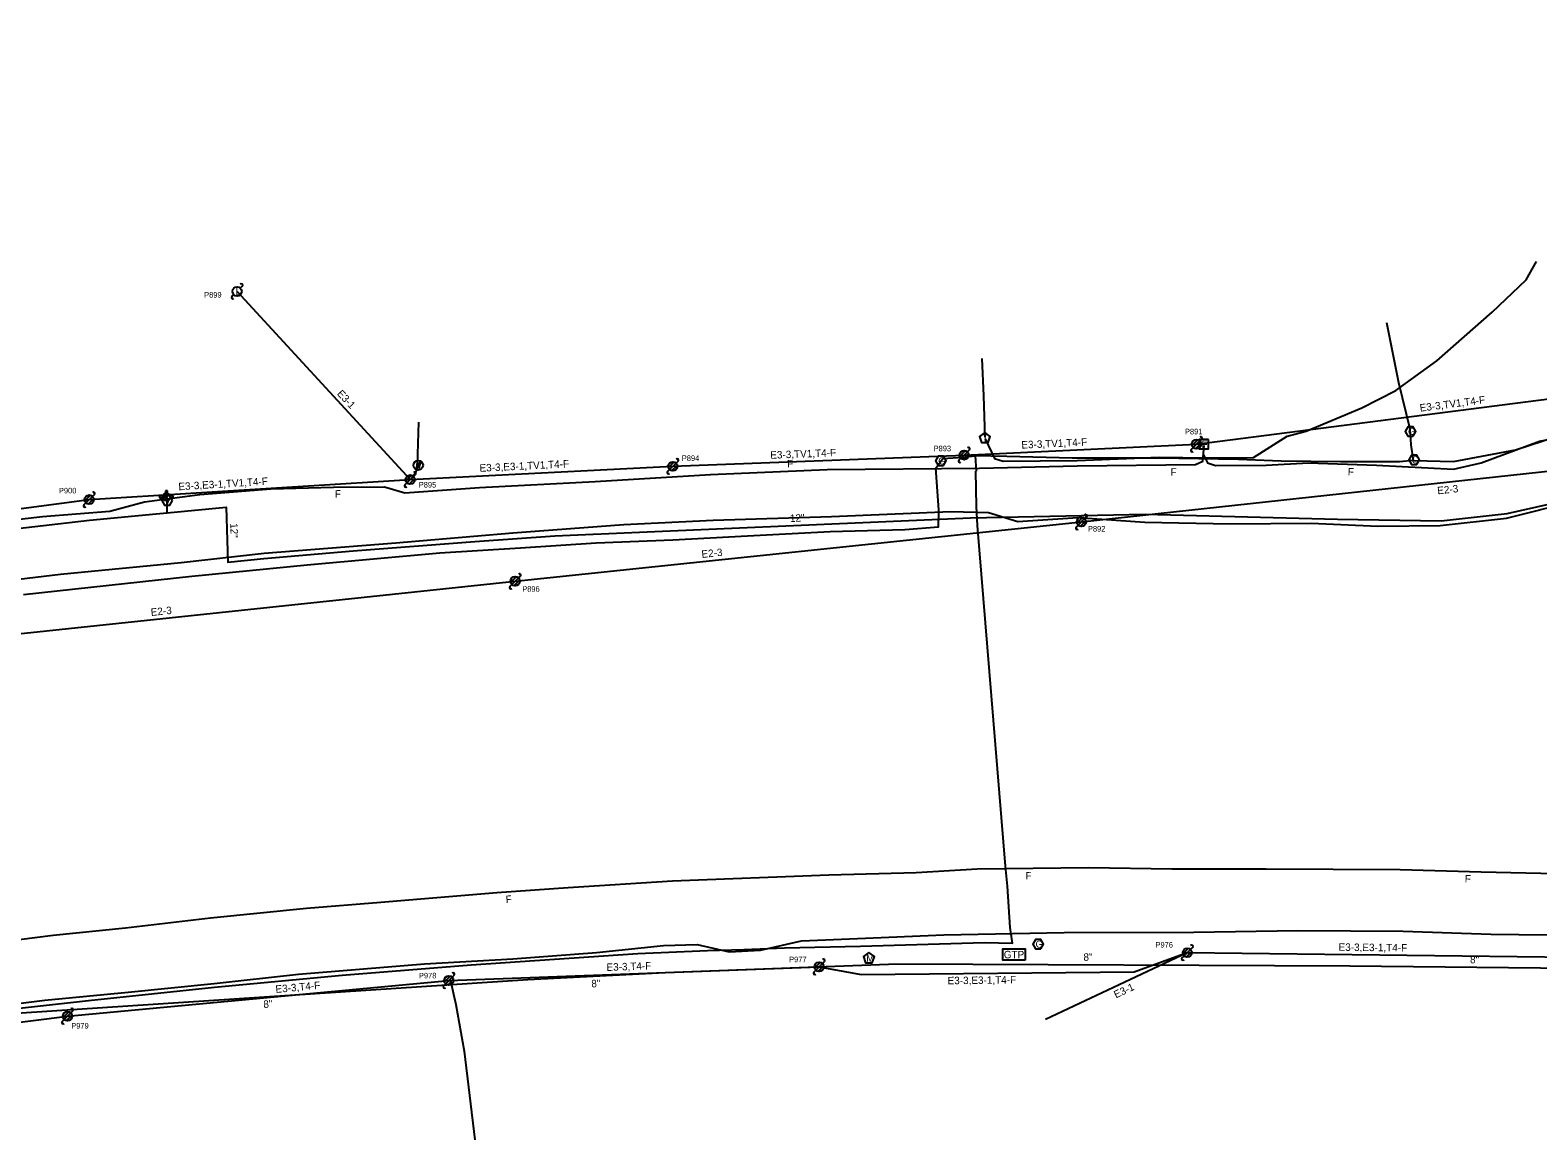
# Model space of a CAD drawing. Extents: x 1741604 to 1825760, y 1164229 to 1194908.
# Drawn here: x 1797796 to 1798607, y 1188088 to 1188684 of the extents above; entities that cross this region are included whole.
import ezdxf

# ---------------------------------------------------------------- set-up
doc = ezdxf.new("R2010")
doc.units = 0
for name, color, linetype in [('RD_EX_SU_Elec', 7, 'Continuous'), ('RD_EX_SU_Gas', 7, 'Continuous'), ('RD_EX_SU_H2O', 7, 'Continuous'), ('RD_EX_SU_Ovhd', 7, 'Continuous'), ('RD_EX_SU_Pole', 7, 'Continuous'), ('RD_EX_SU_Telecom', 7, 'Continuous'), ('RD_EX_SU_TX_H2O', 7, 'Continuous'), ('RD_EX_SU_TX_Pole', 7, 'Continuous'), ('RD_EX_SU_TX_Telecom', 7, 'Continuous')]:
    doc.layers.add(name, color=color, linetype=linetype)

# ---------------------------------------------------------------- blocks, each defined once
blk = doc.blocks.new('SUE_WM')
at = {"layer": 'RD_EX_SU_H2O'}
blk.add_lwpolyline([(0, 3.05), (-2.9, 0.94), (-1.79, -2.47), (1.79, -2.47), (2.9, 0.94)], close=True, dxfattribs=at)
blk.add_text('M', height=3.75, dxfattribs=at).set_placement((-1.43, -1.88))
blk = doc.blocks.new('SUE_GVC')
at = {"layer": 'RD_EX_SU_Gas'}
blk.add_lwpolyline([(1.44, -2.5), (2.89, 0), (1.44, 2.5), (-1.44, 2.5), (-2.89, 0), (-1.44, -2.5)], close=True, dxfattribs=at)
blk.add_text('G', height=3.75, dxfattribs=at).set_placement((-1.34, -1.88))
blk = doc.blocks.new('SUE_TPP')
at = {"layer": 'RD_EX_SU_Telecom'}
blk.add_lwpolyline([(0, 3), (-2.85, 0.93), (-1.76, -2.43), (1.76, -2.43), (2.85, 0.93)], close=True, dxfattribs=at)
blk.add_text('T', height=3.75, dxfattribs=at).set_placement((-1.25, -1.88))
blk = doc.blocks.new('SUE_ETM')
at = {"layer": 'RD_EX_SU_Elec'}
blk.add_lwpolyline([(1.24, 2.04), (0.23, -1.41), (-0.27, 0.46), (-1.03, -2.36), (-0.34, 1.55), (0.22, -0.39)], close=True, dxfattribs=at)
blk.add_circle((0, 0), 2.55, dxfattribs=at)
blk = doc.blocks.new('SUE_WFH')
at = {"layer": 'RD_EX_SU_H2O'}
for p, q in [((-2.01, 0.6), (-3.65, 0.6)), ((-3.65, 0.6), (-3.65, -0.45)), ((-0.48, 3.38), (-0.48, 2.04)), ((0.57, 3.38), (-0.48, 3.38)), ((0.57, 2.02), (0.57, 3.38)), ((3.7, 0.6), (2.01, 0.6)), ((3.7, -0.45), (3.7, 0.6)), ((-3.65, -0.45), (-2.05, -0.45)), ((2.05, -0.45), (3.7, -0.45))]:
    blk.add_line(p, q, dxfattribs=at)
for radius in [2.1, 0.263]:
    blk.add_circle((0, 0), radius, dxfattribs=at)
for start, end in [(163.3387, 192.31502), (74.24552, 103.21276), (347.68498, 16.6613)]:
    blk.add_arc((0, 0), 2.1, start, end, dxfattribs=at)
blk = doc.blocks.new('SUE_WV')
at = {"layer": 'RD_EX_SU_H2O'}
blk.add_lwpolyline([(2.89, 0), (1.44, 2.5), (-1.44, 2.5), (-2.89, 0), (-1.44, -2.5), (1.44, -2.5)], close=True, dxfattribs=at)
blk.add_text('V', height=3.75, dxfattribs=at).set_placement((-1.43, -1.88))

msp = doc.modelspace()

# ---------------------------------------------------------------- linework, layer by layer
at = {"layer": 'RD_EX_SU_Elec'}
for points in [[(1798004.79, 1188453.04), (1798004.66, 1188456.54), (1798005.22, 1188473.7)], [(1798001.22, 1188443.24), (1798003.9, 1188447.11), (1798004.24, 1188448.38)], [(1798022.26, 1188173.57), (1798025.16, 1188160.75), (1798029.65, 1188135.73), (1798035.41, 1188088.07)]]:
    msp.add_lwpolyline(points, dxfattribs=at)
at = {"layer": 'RD_EX_SU_Gas'}
for points in [[(1798540.02, 1188453.1), (1798561.42, 1188452.55), (1798594.68, 1188458.87), (1798616.68, 1188465.98), (1798635.5, 1188476.83), (1798669.38, 1188491.43), (1798687.92, 1188501.53), (1798704.5, 1188511.11), (1798719.12, 1188521.68), (1798742.22, 1188540.09), (1798758.9, 1188555.78), (1798774.34, 1188572.88), (1798802.43, 1188609.18), (1798819.17, 1188635.67), (1798831.94, 1188665.33), (1798832.73, 1188675.73)], [(1798525.4, 1188527.29), (1798531.86, 1188494.99), (1798537.92, 1188470.06), (1798538.41, 1188461.43), (1798539.71, 1188453.05), (1798532.32, 1188452.41), (1798500.7, 1188452.29), (1798468.81, 1188452.77), (1798445.87, 1188453.58), (1798402.97, 1188454.26), (1798356.44, 1188454.27), (1798321.29, 1188455.26), (1798304.33, 1188455.51)], [(1797792.89, 1188381.02), (1797883.32, 1188390.89), (1797945.19, 1188396.98), (1798016.59, 1188403.44), (1798059.98, 1188406.18), (1798100.51, 1188408.83), (1798141.81, 1188410.44), (1798181.84, 1188412.52), (1798226.38, 1188414.99), (1798266.44, 1188416.08), (1798284.61, 1188417.5), (1798284.71, 1188426.53), (1798283.11, 1188448.99), (1798286.92, 1188454.19), (1798297.89, 1188454.93), (1798304.33, 1188455.51), (1798304.77, 1188447.27)], [(1797738.94, 1188153.06), (1797827.69, 1188162.92), (1797895.38, 1188170.03), (1797964.13, 1188176.5), (1798033.35, 1188182.12), (1798122.93, 1188188.15), (1798160.35, 1188189.8), (1798179.98, 1188190.39), (1798201.78, 1188191.3), (1798242.62, 1188192.13), (1798309.37, 1188194.16), (1798324.41, 1188193.75), (1798323.14, 1188202.23), (1798321.69, 1188224.33), (1798320.58, 1188235.17), (1798305.62, 1188418.09), (1798304.96, 1188428.39), (1798304.62, 1188447.39)]]:
    msp.add_lwpolyline(points, dxfattribs=at)
msp.add_lwpolyline([(1798331.09, 1188184.62), (1798319.09, 1188184.62), (1798319.09, 1188190.62), (1798331.09, 1188190.62)], close=True, dxfattribs=at)
at = {"layer": 'RD_EX_SU_H2O'}
for p, q in [((1798301.72, 1188422.21), (1798395.66, 1188424.19)), ((1798078.39, 1188412.53), (1798301.72, 1188422.21)), ((1798137.61, 1188177.95), (1798262.58, 1188182.7)), ((1798262.58, 1188182.7), (1798505.66, 1188181.64)), ((1798505.66, 1188181.64), (1798756.83, 1188179)), ((1797651.95, 1188147.16), (1798063.79, 1188174.26)), ((1798063.79, 1188174.26), (1798137.61, 1188177.95))]:
    msp.add_line(p, q, dxfattribs=at)
for points in [[(1798395.66, 1188424.19), (1798464.51, 1188422.44), (1798499.05, 1188421.5), (1798554.83, 1188420.73), (1798590.2, 1188424.62), (1798613.36, 1188429.79), (1798642.06, 1188437.41), (1798666.06, 1188447.65), (1798696.65, 1188463.78), (1798729.84, 1188484.09), (1798749.61, 1188498.15)], [(1797150.37, 1188316.12), (1797152.28, 1188309.78), (1797177.44, 1188315.15), (1797233.5, 1188327.84), (1797278.93, 1188337.07), (1797336.23, 1188346.78), (1797380.95, 1188356.35), (1797444.61, 1188369.17), (1797512.17, 1188378.38), (1797550.95, 1188385.16), (1797589.68, 1188391.31), (1797635.24, 1188397.02), (1797695.71, 1188404.5), (1797752.4, 1188412.16), (1797828.2, 1188420.96), (1797864.18, 1188424.5), (1797870.03, 1188425), (1797870.01, 1188429.58), (1797869.79, 1188432.74)], [(1797870.03, 1188425), (1797901.67, 1188428.06), (1797902.58, 1188398.42), (1797922.02, 1188400.35), (1797969.92, 1188404.62), (1798035.33, 1188409.61), (1798078.39, 1188412.53)]]:
    msp.add_lwpolyline(points, dxfattribs=at)
at = {"layer": 'RD_EX_SU_Ovhd'}
for p, q in [((1797907.57, 1188543.94), (1798000.66, 1188442.8)), ((1798423.29, 1188461.79), (1798648.97, 1188490.91)), ((1798141.81, 1188449.95), (1798298.38, 1188456.02)), ((1798298.38, 1188456.02), (1798423.29, 1188461.79)), ((1798361.37, 1188420.07), (1798718.12, 1188458.87)), ((1798000.66, 1188442.8), (1798141.81, 1188449.95)), ((1797828.15, 1188432.05), (1798000.66, 1188442.8)), ((1797680, 1188412.7), (1797828.15, 1188432.05)), ((1798057.02, 1188388.18), (1798361.37, 1188420.07)), ((1797704.48, 1188350.9), (1798057.02, 1188388.18)), ((1798342.15, 1188152.97), (1798418.32, 1188188.64)), ((1798418.32, 1188188.64), (1798625.21, 1188186.16)), ((1798021.47, 1188173.66), (1798220.42, 1188181.01)), ((1797816.46, 1188154.52), (1798021.47, 1188173.66)), ((1797662.12, 1188135.12), (1797816.46, 1188154.52))]:
    msp.add_line(p, q, dxfattribs=at)
msp.add_lwpolyline([(1798220.42, 1188181.01), (1798242.98, 1188176.98), (1798389.75, 1188178.38), (1798418.32, 1188188.64)], dxfattribs=at)
at = {"layer": 'RD_EX_SU_Pole'}
for p, q in [((1797909.34, 1188545.71), (1797910.4, 1188546.77)), ((1797904.74, 1188541.11), (1797905.8, 1188542.17)), ((1798420.87, 1188461.14), (1798423.93, 1188464.2)), ((1798421.52, 1188460.02), (1798425.05, 1188463.56)), ((1798425.05, 1188463.56), (1798426.12, 1188464.62)), ((1798295.96, 1188455.37), (1798299.02, 1188458.43)), ((1798296.61, 1188454.25), (1798300.15, 1188457.79)), ((1798297.73, 1188453.6), (1798300.79, 1188456.67)), ((1798300.15, 1188457.79), (1798301.21, 1188458.85)), ((1798420.46, 1188458.96), (1798421.52, 1188460.02)), ((1798422.64, 1188459.37), (1798425.7, 1188462.44)), ((1798138.99, 1188447.13), (1798140.05, 1188448.19)), ((1798139.4, 1188449.31), (1798142.46, 1188452.37)), ((1798140.05, 1188448.19), (1798143.58, 1188451.72)), ((1798141.17, 1188447.54), (1798144.23, 1188450.6)), ((1798143.58, 1188451.72), (1798144.64, 1188452.78)), ((1798295.55, 1188453.19), (1798296.61, 1188454.25)), ((1797997.83, 1188439.97), (1797998.89, 1188441.03)), ((1797998.25, 1188442.15), (1798001.31, 1188445.22)), ((1797998.89, 1188441.03), (1798002.43, 1188444.57)), ((1798000.01, 1188440.39), (1798003.08, 1188443.45)), ((1798002.43, 1188444.57), (1798003.49, 1188445.63)), ((1797825.74, 1188431.41), (1797828.8, 1188434.47)), ((1797826.38, 1188430.29), (1797829.92, 1188433.82)), ((1797827.5, 1188429.64), (1797830.57, 1188432.7)), ((1797829.92, 1188433.82), (1797830.98, 1188434.88)), ((1797825.32, 1188429.23), (1797826.38, 1188430.29)), ((1798363.14, 1188421.84), (1798364.2, 1188422.9)), ((1798358.54, 1188417.25), (1798359.6, 1188418.31)), ((1798358.95, 1188419.43), (1798362.01, 1188422.49)), ((1798359.6, 1188418.31), (1798363.14, 1188421.84)), ((1798360.72, 1188417.66), (1798363.78, 1188420.72)), ((1798054.6, 1188387.54), (1798057.66, 1188390.6)), ((1798058.78, 1188389.95), (1798059.84, 1188391.01)), ((1798054.19, 1188385.35), (1798055.25, 1188386.41)), ((1798055.25, 1188386.41), (1798058.78, 1188389.95)), ((1798056.37, 1188385.77), (1798059.43, 1188388.83)), ((1798415.9, 1188187.99), (1798418.97, 1188191.06)), ((1798416.55, 1188186.87), (1798420.09, 1188190.41)), ((1798417.67, 1188186.23), (1798420.73, 1188189.29)), ((1798420.09, 1188190.41), (1798421.15, 1188191.47)), ((1798218, 1188180.36), (1798221.07, 1188183.42)), ((1798218.65, 1188179.24), (1798222.19, 1188182.78)), ((1798219.77, 1188178.59), (1798222.83, 1188181.65)), ((1798222.19, 1188182.78), (1798223.25, 1188183.84)), ((1798415.49, 1188185.81), (1798416.55, 1188186.87)), ((1798018.64, 1188170.83), (1798019.71, 1188171.89)), ((1798019.06, 1188173.02), (1798022.12, 1188176.08)), ((1798019.71, 1188171.89), (1798023.24, 1188175.43)), ((1798020.83, 1188171.25), (1798023.89, 1188174.31)), ((1798023.24, 1188175.43), (1798024.3, 1188176.49)), ((1798217.59, 1188178.18), (1798218.65, 1188179.24)), ((1797814.05, 1188153.87), (1797817.11, 1188156.93)), ((1797814.7, 1188152.75), (1797818.23, 1188156.29)), ((1797818.23, 1188156.29), (1797819.29, 1188157.35)), ((1797813.64, 1188151.69), (1797814.7, 1188152.75)), ((1797815.82, 1188152.1), (1797818.88, 1188155.17))]:
    msp.add_line(p, q, dxfattribs=at)
for centre in [(1797907.57, 1188543.94), (1798423.29, 1188461.79), (1798298.38, 1188456.02), (1798141.81, 1188449.95), (1798000.66, 1188442.8), (1797828.15, 1188432.05), (1798361.37, 1188420.07), (1798057.02, 1188388.18), (1798418.32, 1188188.64), (1798220.42, 1188181.01), (1798021.47, 1188173.66), (1797816.46, 1188154.52)]:
    msp.add_circle(centre, 2.5, dxfattribs=at)
for centre, start, end in [((1797909.87, 1188547.3), 315, 135), ((1797905.27, 1188540.58), 135, 315), ((1798425.59, 1188465.15), 315, 135), ((1798300.68, 1188459.38), 315, 135), ((1798420.99, 1188458.43), 135, 315), ((1798144.11, 1188453.31), 315, 135), ((1798296.08, 1188452.66), 135, 315), ((1797998.36, 1188439.44), 135, 315), ((1798002.96, 1188446.16), 315, 135), ((1798139.52, 1188446.6), 135, 315), ((1797830.45, 1188435.41), 315, 135), ((1797825.85, 1188428.7), 135, 315), ((1798363.67, 1188423.43), 315, 135), ((1798359.07, 1188416.72), 135, 315), ((1798059.31, 1188391.54), 315, 135), ((1798054.72, 1188384.82), 135, 315), ((1798420.62, 1188192), 315, 135), ((1798222.72, 1188184.37), 315, 135), ((1798416.02, 1188185.28), 135, 315), ((1798023.77, 1188177.02), 315, 135), ((1798218.12, 1188177.65), 135, 315), ((1798019.17, 1188170.3), 135, 315), ((1797818.76, 1188157.88), 315, 135), ((1797814.17, 1188151.16), 135, 315)]:
    msp.add_arc(centre, 0.75, start, end, dxfattribs=at)
at = {"layer": 'RD_EX_SU_Telecom'}
for points in [[(1798426.98, 1188456.06), (1798429.11, 1188451.85), (1798433.5, 1188450.35), (1798460.68, 1188450.49), (1798483.53, 1188451.77), (1798520.04, 1188450.56), (1798561.41, 1188448.34), (1798576.32, 1188451.82), (1798607.67, 1188463.55), (1798626.32, 1188467.05), (1798668.2, 1188483.11), (1798687.44, 1188493.71), (1798705.93, 1188506.21), (1798736.47, 1188529.82), (1798758.54, 1188543.67), (1798781.25, 1188567.72), (1798795.21, 1188585.11), (1798815.44, 1188613.84), (1798825.56, 1188632.61), (1798837.05, 1188658.15), (1798847.31, 1188684.3)], [(1798309.64, 1188464.65), (1798314.62, 1188454.11), (1798319.29, 1188452.65), (1798359.15, 1188453.13), (1798403.21, 1188454.79), (1798428.64, 1188454.53), (1798453.89, 1188454.73), (1798472.01, 1188466.24), (1798482.21, 1188468.91), (1798512.16, 1188481.31), (1798530.3, 1188490.62), (1798552.36, 1188506.62), (1798582.13, 1188532.79), (1798600.38, 1188550.18), (1798606, 1188559.92)], [(1798307.89, 1188507.83), (1798308.83, 1188487.87), (1798309.56, 1188465.59)], [(1797599.69, 1188402.69), (1797602.78, 1188398.4), (1797607.39, 1188395.86), (1797634.77, 1188398.33), (1797667.95, 1188404.83), (1797706.55, 1188411.49), (1797764.24, 1188418.52), (1797803.02, 1188422.9), (1797839.16, 1188425.94), (1797857.83, 1188430.92), (1797887.61, 1188434.79), (1797925.68, 1188437.9), (1797959.41, 1188438.8), (1797986.77, 1188438.97), (1797997.76, 1188435.68), (1798037.94, 1188438.51), (1798099.98, 1188441.74), (1798161.98, 1188445.48), (1798224.83, 1188448.24), (1798306.55, 1188448.95), (1798359.19, 1188450.24), (1798422.72, 1188451.01), (1798426.7, 1188452.69), (1798427.41, 1188461.14)], [(1797746.79, 1188384.17), (1797812.75, 1188392.07), (1797877.48, 1188398.23), (1797922.19, 1188403.32), (1797992.9, 1188408.77), (1798055.88, 1188414.18), (1798115.42, 1188418.64), (1798163.49, 1188421), (1798227.04, 1188423), (1798291.27, 1188425.62), (1798311.42, 1188425.18), (1798327.16, 1188420.34), (1798359.48, 1188422.46), (1798395.44, 1188419.94), (1798441.35, 1188419.12), (1798484.89, 1188419.42), (1798520.62, 1188417.82), (1798554.23, 1188418.17), (1798589.8, 1188422.02), (1798604.92, 1188425.94), (1798641.8, 1188435.36)], [(1797773.45, 1188193.62), (1797808.75, 1188197.97), (1797847.55, 1188202.05), (1797893.32, 1188207.34), (1797944.85, 1188212.59), (1797984.79, 1188215.83), (1798047.26, 1188220.91), (1798085.46, 1188223.69), (1798141.67, 1188227.15), (1798225.72, 1188230.39), (1798272.51, 1188231.68), (1798305.4, 1188233.6), (1798365.44, 1188234.41), (1798410.04, 1188233.6), (1798460.62, 1188233.65), (1798532.65, 1188233.33), (1798576.2, 1188232.14), (1798624.25, 1188231.08)], [(1797759.76, 1188157.55), (1797804.33, 1188163.09), (1797849.11, 1188167.41), (1797895.25, 1188172.11), (1797940.68, 1188177.05), (1798008.34, 1188182.64), (1798055.76, 1188185.39), (1798100.83, 1188188.77), (1798136.79, 1188192.56), (1798154.92, 1188193), (1798172.08, 1188189.02), (1798188.91, 1188189.92), (1798211, 1188194.96), (1798241.13, 1188196.21), (1798287.46, 1188198.22), (1798352.07, 1188199.51), (1798421.8, 1188199.64), (1798477.78, 1188200.48), (1798534.35, 1188200.11), (1798581.38, 1188198.52), (1798626.82, 1188198.06)]]:
    msp.add_lwpolyline(points, dxfattribs=at)
msp.add_lwpolyline([(1798429.66, 1188464.32), (1798424.66, 1188464.32), (1798424.66, 1188459.32), (1798429.66, 1188459.32)], close=True, dxfattribs=at)

# ---------------------------------------------------------------- block references
at = {"layer": 'RD_EX_SU_Elec'}
msp.add_blockref('SUE_ETM', (1798004.98, 1188450.51), dxfattribs=at)
at = {"layer": 'RD_EX_SU_Gas'}
for p in [(1798538.26, 1188468.74), (1798285.79, 1188452.87), (1798540.26, 1188453.42), (1798338.1, 1188193.23)]:
    msp.add_blockref('SUE_GVC', p, dxfattribs=at)
at = {"layer": 'RD_EX_SU_H2O'}
for name, p in [('SUE_WFH', (1797869.63, 1188433.46)), ('SUE_WV', (1797870, 1188431.51)), ('SUE_WM', (1798247.21, 1188185.67))]:
    msp.add_blockref(name, p, dxfattribs=at)
at = {"layer": 'RD_EX_SU_Telecom'}
msp.add_blockref('SUE_TPP', (1798309.43, 1188465.12), dxfattribs=at)

# ---------------------------------------------------------------- texts
at = {"layer": 'RD_EX_SU_Gas'}
msp.add_text('GTP', height=4, dxfattribs=at).set_placement((1798319.66, 1188185.62))
at = {"layer": 'RD_EX_SU_Ovhd'}
for s, rotation, p in [('E3-1', 312.62652, (1797961.05, 1188488.79)), ('E3-3,TV1,T4-F', 7.35174, (1798543.49, 1188479.31)), ('E3-3,TV1,T4-F', 2.64477, (1798329.22, 1188459.45)), ('E3-3,TV1,T4-F', 2.21846, (1798194.24, 1188453.99)), ('E3-3,E3-1,TV1,T4-F', 2.90085, (1798038.01, 1188446.99)), ('E3-3,E3-1,TV1,T4-F', 3.56466, (1797876.18, 1188437.05)), ('E2-3', 6.20681, (1798552.89, 1188434.87)), ('E2-3', 5.98192, (1798157.43, 1188400.71)), ('E2-3', 6.03634, (1797861.42, 1188369.51)), ('E3-3,E3-1,T4-F', 359.31378, (1798499.59, 1188189.67)), ('E3-3,T4-F', 2.11438, (1798106.21, 1188178.79)), ('E3-3,T4-F', 5.33482, (1797928.44, 1188166.98)), ('E3-3,E3-1,T4-F', 0.79427, (1798289.49, 1188171.62)), ('E3-1', 25.0941, (1798379.94, 1188164.04))]:
    msp.add_text(s, height=4, rotation=rotation, dxfattribs=at).set_placement(p)
at = {"layer": 'RD_EX_SU_Pole'}
msp.add_text('L', height=4, dxfattribs=at).set_placement((1797906.71, 1188541.94))
at = {"layer": 'RD_EX_SU_Telecom'}
msp.add_text('F', height=4, dxfattribs=at).set_placement((1798425.92, 1188459.82))
at = {"layer": 'RD_EX_SU_TX_H2O'}
for s, rotation, p in [('12"', 2.48175, (1798204.82, 1188420.01)), ('12"', 271.76186, (1797903.93, 1188419.36)), ('8"', 359.75131, (1798362.49, 1188184.26)), ('8"', 359.3983, (1798570.26, 1188182.96)), ('8"', 2.86381, (1798098.08, 1188169.96)), ('8"', 3.76406, (1797921.85, 1188158.9))]:
    msp.add_text(s, height=4, rotation=rotation, dxfattribs=at).set_placement(p)
at = {"layer": 'RD_EX_SU_TX_Pole'}
for s, p in [('P899', (1797889.9, 1188540.6)), ('P891', (1798417.06, 1188467.13)), ('P894', (1798146.63, 1188452.82)), ('P893', (1798281.97, 1188458.03)), ('P895', (1798005.25, 1188438.56)), ('P900', (1797811.86, 1188435.39)), ('P892', (1798364.91, 1188414.9)), ('P896', (1798060.87, 1188382.55)), ('P976', (1798401.2, 1188191.38)), ('P977', (1798204.3, 1188183.49)), ('P978', (1798005.35, 1188174.8)), ('P979', (1797818.48, 1188147.86))]:
    msp.add_text(s, height=3, dxfattribs=at).set_placement(p)
at = {"layer": 'RD_EX_SU_TX_Telecom'}
for rotation, p in [(2.51823, (1798203.32, 1188449.3)), (0.69338, (1798409.35, 1188444.85)), (358.09124, (1798504.49, 1188445.07)), (1.53014, (1797960.23, 1188433.11)), (0.77359, (1798331.38, 1188227.95)), (358.43884, (1798567.38, 1188226.38)), (4.16664, (1798052.13, 1188215.25))]:
    msp.add_text('F', height=4, rotation=rotation, dxfattribs=at).set_placement(p)

doc.saveas('drawing.dxf')
